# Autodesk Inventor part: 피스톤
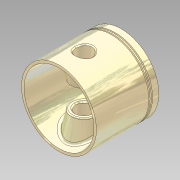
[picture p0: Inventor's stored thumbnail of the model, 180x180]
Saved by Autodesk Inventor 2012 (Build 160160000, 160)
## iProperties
Manager: KYOUNG IL JANG
Company: 한국ATC센터
Created: 2012-10
Part Number: 피스톤
Document SubType Name: Modeling
Density: 1 g/cm^3
Checked By: KYOUNG IL JANG
Vendor: CBT Solutions
Designer: KYOUNG IL JANG
Material: 기본값
Author: KYOUNG IL JANG
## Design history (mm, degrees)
sketch "스케치1"
  geometry: L1 (0, 0)-(0, 50); L2 (0, 50)-(30, 50); L3 (30, 50)-(30, 45); L4 (30, 45)-(28, 45); L5 (28, 45)-(28, 44); L6 (28, 44)-(30, 44); L7 (30, 44)-(30, 43); L8 (30, 43)-(28, 43); L9 (28, 43)-(28, 42); L10 (28, 42)-(30, 42); L11 (30, 42)-(30, 0); L12 (30, 0)-(28, 0); L13 (28, 0)-(23, 45); L14 (23, 45)-(0, 45)
  constraints: 28 end point, 10 parallel, 5 collinear, 2 perpendicular, 2 point on line, 1 vertical
  dimensions: "d0" = 50 distance of L1.start L1.end; "d1" = 60 diameter of L3 L1; "d2" = 5 distance between parallel lines of L2 L14; "d3" = 2 distance of L11.end L12.end; "d5" = 5 distance of L2.end L3.end; "d6" = 1 distance of L4.end L5.end; "d7" = 2 distance of L9.end L10.end; "d26" = 46 diameter of L13.end L1
revolve "회전1" sketch "스케치1" stored, may be unused: angle "d8" = 90 deg
node "작업 평면1"
sketch "스케치2"
  geometry: L1 (-28, 0)-(28, 0) reference; C1 r 10 at (0, 20); C2 r 6.5 at (0, 20); 1 further point
  constraints: 2 centre point, 1 coincident, 1 vertical alignment
  dimensions: "d10" = 20 diameter of C1; "d13" = 20 distance from line of C1.centre L1; "d14" = 13 diameter of C2
extrude "돌출1" join sketch "스케치2" stored distance "d11" = 10; taper "d12" = 12 deg
extrude "돌출2" cut sketch "스케치2" stored distance "d15" = 10; taper "d16" = 0 deg
fillet "모깎기1" dims "d17" = 2, "d21" = 3
chamfer "모따기1" distance "d18" = 1; stored, may be unused: second distance "d19" = 2, angle "d20" = 45 deg
chamfer "모따기2" distance "d22" = 1; stored, may be unused: second distance "d23" = 2, angle "d24" = 45 deg
fillet "모깎기2" dims "d25" = 1
node "솔리드1"
mirror "대칭1"
